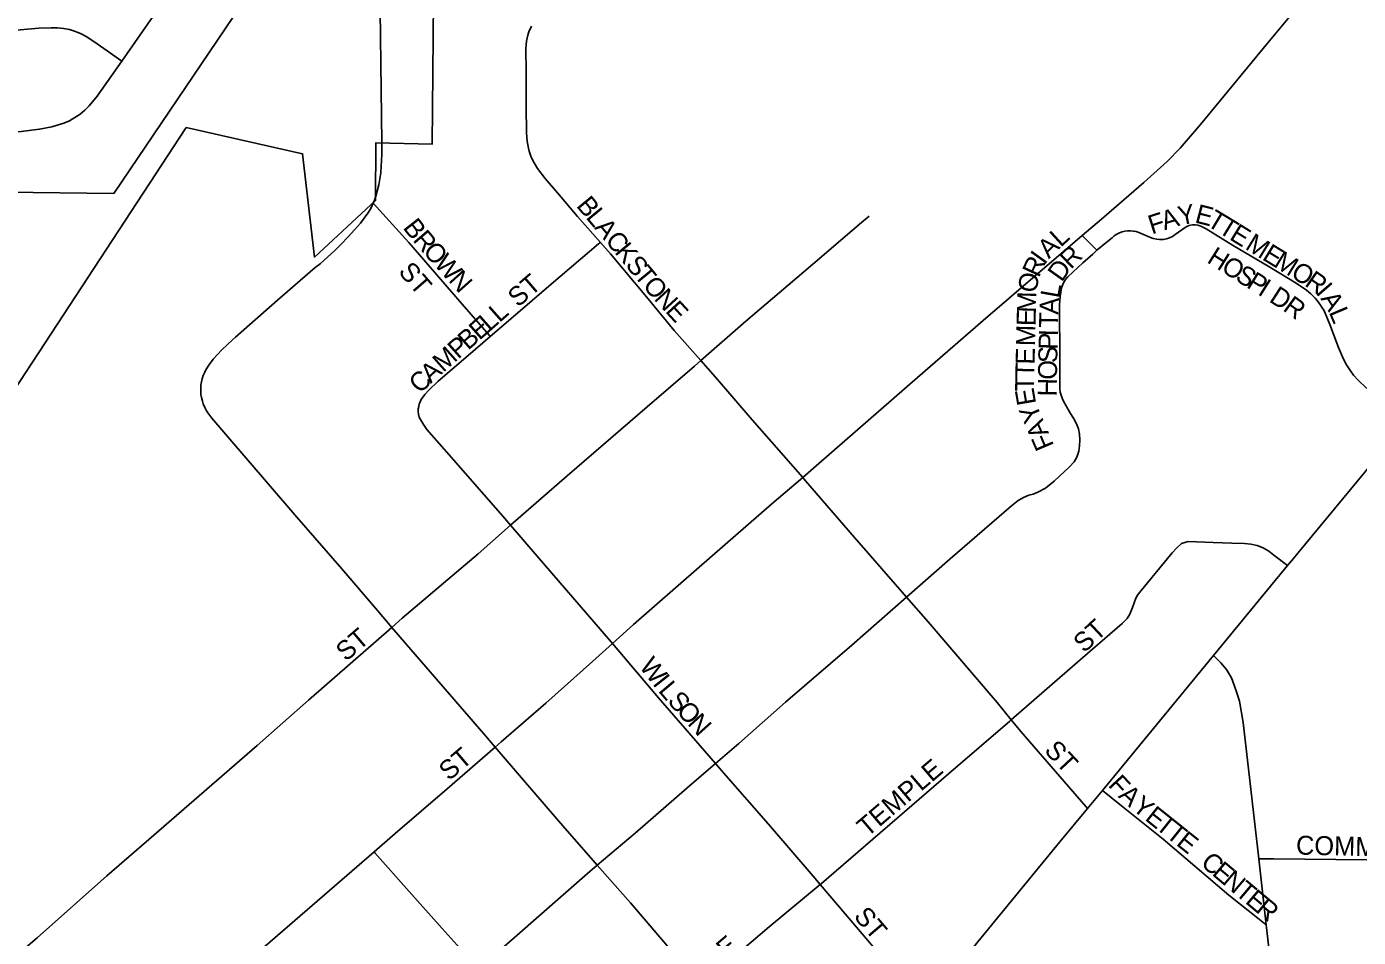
# Model space of a CAD drawing. Extents: x -51392 to 1635000, y 156707 to 696232.
# Drawn here: x 139153 to 142661, y 489774 to 492173 of the extents above; entities that cross this region are included whole.
import ezdxf

# ---------------------------------------------------------------- set-up
doc = ezdxf.new("R2010")
doc.units = 0
for name, color, linetype in [('GM_X_City_Street', 7, 'Continuous'), ('GM_X_City_Street_Text', 7, 'Continuous'), ('GM_X_Corporation', 7, 'Continuous'), ('GM_X_State_Route', 7, 'Continuous'), ('GM_X_US_Route', 7, 'Continuous')]:
    doc.layers.add(name, color=color, linetype=linetype)

msp = doc.modelspace()

# ---------------------------------------------------------------- linework, layer by layer
at = {"layer": 'GM_X_City_Street'}
for points in [[(141933.2, 491622.4), (141984, 491665.8), (142095.8, 491762.2), (142156.8, 491817.3), (142191.3, 491852.7), (142245.3, 491914.6), (142422.5, 492129.9), (142610.7, 492357.2), (142821, 492608.8), (142845.6, 492634.5)], [(139403.9, 492081.4), (139452.7, 492150.8), (139527, 492259.2), (139562.4, 492314.4), (139577.6, 492343.6), (139590.4, 492373.8), (139601, 492404.9), (139609.4, 492436.6), (139615.5, 492468.9), (139618.9, 492501.5), (139621.8, 492600), (139621.8, 492601.7)], [(138389, 492100.2), (138467.7, 492106.2), (138696, 492125.6), (138859.1, 492139.3), (139185.2, 492168.5), (139217.9, 492169.8), (139234.3, 492169.4), (139250.6, 492167.7), (139266.6, 492164.7), (139282.3, 492160), (139297.3, 492153.7), (139311.8, 492146), (139338.8, 492127.6), (139365.5, 492108.6), (139403.9, 492081.4)], [(140664.3, 491604.2), (140603.9, 491672.4), (140551.1, 491735.2), (140518.7, 491772.5), (140498.5, 491799.1), (140489.7, 491813.5), (140482.5, 491828.8), (140479.2, 491837.1), (140476.7, 491845), (140475.2, 491852.3), (140473.3, 491861.4), (140471.8, 491871), (140470.7, 491880.6), (140470, 491894.6), (140469.1, 491960.6), (140469.1, 492075.4), (140468.4, 492091.3), (140468.3, 492104.1), (140468.2, 492114.4), (140468.9, 492125.1), (140469.8, 492133.9), (140471.3, 492142), (140473.3, 492150.4), (140476.2, 492158.5), (140483, 492174)], [(138411.3, 491804.6), (138518.5, 491829.1), (138583.2, 491840.3), (138632, 491846.8), (138779.1, 491861.4), (138975.1, 491880.8), (139138.6, 491896.4), (139187.5, 491902.4), (139219.7, 491908.9), (139251.1, 491918.4), (139266.2, 491924.9), (139280.5, 491932.9), (139294, 491942.2), (139306.6, 491952.8), (139318.2, 491964.4), (139339.1, 491989.7), (139403.9, 492081.4)], [(140374.2, 491356.9), (140371.2, 491360.3), (140300, 491441.6), (140160.3, 491604.4), (140066.2, 491707.7)], [(140928.8, 491293), (141047.8, 491397.2), (141135.2, 491471.6), (141247.6, 491567.1), (141347.1, 491652.4), (141372.2, 491673.4)], [(141972.1, 491584), (141999.7, 491606.7), (142011.9, 491616.7), (142017.7, 491621.3), (142024.7, 491625.8), (142031.6, 491629.3), (142038.4, 491631.9), (142045.6, 491633.8), (142053, 491634.7), (142060.5, 491634.9), (142067.8, 491634.1), (142075, 491632.9), (142082.7, 491630.4), (142113.1, 491617.5), (142119.9, 491615.1), (142129.5, 491612.5), (142137, 491611.6), (142146.6, 491611.8), (142155.4, 491613.5), (142163.3, 491616.3), (142171.3, 491620.3), (142178.3, 491624.8), (142204.2, 491643.7), (142210.6, 491647.3), (142215.2, 491648.9), (142218.6, 491649.8), (142223.9, 491650.3), (142231.4, 491650.5), (142237.8, 491649.5), (142245.9, 491646.9), (142252.9, 491643.9), (142260.2, 491639.8), (142329.1, 491596.7), (142427.7, 491539), (142497.2, 491497.1), (142523.7, 491478.9), (142535.8, 491468.7), (142541.8, 491463), (142546.9, 491457.4), (142552.1, 491451.5), (142556.9, 491445.2), (142561.2, 491439.2), (142565.7, 491432.1), (142569.5, 491425.8), (142573.4, 491418.2), (142585.7, 491388.6), (142608.5, 491327.6), (142621.4, 491297.1), (142629.1, 491282.4), (142638.1, 491268.4), (142648.2, 491255.1), (142659.2, 491242.7), (142682.9, 491219.7)], [(141197.2, 490985.6), (141240, 491022.2), (141499.8, 491248.2), (141672.9, 491398.9), (141809.4, 491516.7), (141933.2, 491622.4)], [(141933.2, 491622.4), (141945.2, 491610.7), (141962.2, 491593.8), (141972.1, 491584)], [(140374.2, 491356.9), (140434.3, 491408.6), (140535, 491494.3), (140659.8, 491600.4), (140664.3, 491604.2)], [(140928.8, 491293), (140858.9, 491372.2), (140785.5, 491460.8), (140690.9, 491574.1), (140664.3, 491604.2)], [(141746.7, 490910.8), (141765.1, 490925.1), (141778.4, 490932.4), (141792.6, 490938.4), (141804, 490941.7), (141816.8, 490946.7), (141836.6, 490957.6), (141859.6, 490975.9), (141900.3, 491013.2), (141912, 491026.9), (141919.6, 491039.1), (141924.1, 491054.9), (141926.5, 491068.9), (141927.4, 491084.9), (141926.2, 491099.7), (141923.5, 491113.1), (141918.5, 491126.4), (141911.3, 491140), (141900, 491158), (141883.9, 491186.2), (141880.4, 491194), (141877.5, 491201.7), (141875.7, 491209.8), (141874.5, 491218.5), (141874.1, 491293.3), (141873.8, 491440.1), (141875, 491462.3), (141876.9, 491473), (141879.2, 491484.5), (141883.7, 491497.9), (141889, 491507), (141895.5, 491514.1), (141934.6, 491550.3), (141960.9, 491573.6), (141972.1, 491584)], [(140192.2, 491191.1), (140202.1, 491203.5), (140213, 491215.4), (140236.3, 491237.9), (140335.1, 491323.3), (140374.2, 491356.9)], [(140427.9, 490859.6), (140576.7, 490989.8), (140787.8, 491171.7), (140912.2, 491278.4), (140928.8, 491293)], [(141197.2, 490985.6), (141064, 491137.2), (140967.7, 491249.1), (140928.8, 491293)], [(140427.9, 490859.6), (140412.6, 490877.5), (140271.9, 491037.8), (140207.7, 491111.9), (140198.4, 491124.8), (140190.4, 491138), (140187.6, 491144.4), (140185.4, 491151.8), (140184.4, 491159.4), (140184.9, 491166.5), (140186.1, 491172.5), (140187.5, 491178.3), (140192.2, 491191.1)], [(140696.1, 490547.8), (140751.5, 490597.9), (140924.6, 490749), (141115.5, 490915.6), (141197.2, 490985.6)], [(141470.8, 490670.3), (141441.6, 490703.9), (141333.4, 490827.5), (141205, 490976.7), (141197.2, 490985.6)], [(141470.8, 490670.3), (141585.8, 490770.8), (141695.1, 490865.9), (141746.7, 490910.8)], [(140115.2, 490590.7), (140142.7, 490614.7), (140342.4, 490784.6), (140427.9, 490859.6)], [(140696.1, 490547.8), (140668.8, 490579.9), (140497.7, 490778.2), (140427.9, 490859.6)], [(142058.7, 490625.1), (142065.9, 490642.7), (142070.3, 490655.1), (142074.8, 490667.9), (142079, 490675.6), (142084.7, 490683.6), (142170.6, 490787), (142181.5, 490799.5), (142194.8, 490811.2), (142212.3, 490816.6), (142278.6, 490814.3), (142327.6, 490812.5), (142360.7, 490811.1), (142377.4, 490809.6), (142394.1, 490806.3), (142410.2, 490800.1), (142424.7, 490791.1), (142437.7, 490781.1), (142474, 490753.2)], [(140967.2, 490232.3), (141028.8, 490285.2), (141152.1, 490393.7), (141326.2, 490543.7), (141470.8, 490670.3)], [(141746.6, 490347), (141709, 490392.6), (141527.7, 490604.8), (141470.8, 490670.3)], [(141746.6, 490347), (141915, 490494.1), (142038.9, 490600.7), (142051.4, 490614.4), (142058.7, 490625.1)], [(139121.4, 489722.3), (139180.9, 489772.6), (139364.6, 489936), (139488.8, 490043), (139760.9, 490279.3), (139896.1, 490398.7), (140115.2, 490590.7)], [(140387, 490275.1), (140403.2, 490289.1), (140520.6, 490391.2), (140643.8, 490500.4), (140696.1, 490547.8)], [(140967.2, 490232.3), (140817.1, 490405.4), (140696.1, 490547.8)], [(142398.3, 489981.2), (142357.3, 490340), (142347.4, 490396.2), (142341.2, 490415.7), (142333.8, 490438.8), (142326.1, 490457.6), (142313.3, 490480), (142298.1, 490496.8), (142279.1, 490516.1)], [(141243.6, 489913.5), (141247.1, 489916.4), (141581.5, 490204.8), (141742.6, 490343.5), (141746.6, 490347)], [(141947.5, 490113.6), (141942.7, 490119.2), (141874.5, 490197.9), (141771.6, 490316.7), (141746.6, 490347)], [(140068.3, 489999.1), (140124.2, 490047.5), (140260.7, 490165.3), (140387, 490275.1)], [(140656.2, 489964.8), (140755.7, 490048.7), (140891.9, 490167.5), (140967.2, 490232.3)], [(141243.6, 489913.5), (141224.7, 489935.8), (141107.1, 490072.2), (140988.6, 490207.7), (140967.2, 490232.3)], [(141986.5, 490160.8), (142032.4, 490124.1), (142146.5, 490032.9), (142319.1, 489885.1), (142396.2, 489824.9), (142418.2, 489807.7)], [(139390.1, 489412.2), (139467.5, 489478.6), (139690.2, 489672.2), (139950.7, 489897.3), (140068.3, 489999.1)], [(140343.2, 489691.3), (140334.8, 489700.7), (140247.5, 489797.5), (140160.8, 489894.7), (140070.5, 489996.6), (140068.3, 489999.1)], [(140343.2, 489691.3), (140445.4, 489780), (140630.3, 489942.8), (140656.2, 489964.8)], [(142398.3, 489981.2), (142437.9, 489980.9), (142519.6, 489980.1), (142764.5, 489977.3), (142911.3, 489974.7), (143172.6, 489970.8), (143239.2, 489970.4)], [(142418.2, 489807.7), (142398.3, 489981.2)], [(140931, 489647), (140996.8, 489706), (141108.8, 489801.6), (141243.6, 489913.5)], [(141504.5, 489574.2), (141492.9, 489600.8), (141485.3, 489615), (141477.2, 489627.4), (141462.6, 489646.7), (141424.3, 489697.2), (141383.7, 489748.8), (141309.2, 489835.9), (141243.6, 489913.5)], [(142430.4, 489701), (142418.2, 489807.7)]]:
    msp.add_lwpolyline(points, dxfattribs=at)
at = {"layer": 'GM_X_Corporation'}
msp.add_lwpolyline([(139780.3, 492322.4), (139382.9, 491732.9), (138531.2, 491743.3), (138447.1, 490541.3), (138625.9, 490463), (138741, 490547.5), (138698.5, 490572.2), (139573.9, 491906.7), (139880, 491837.7), (139911.2, 491565.8), (140072.1, 491715), (140073.3, 491866.9), (140221.8, 491863.1), (140226.3, 492428.6)], dxfattribs=at)
at = {"layer": 'GM_X_State_Route'}
for points in [[(140089.1, 491867.4), (140082.4, 492354.8), (140081.9, 492392.3), (140081.3, 492432.4), (140081, 492479), (140080.7, 492519.1), (140080.4, 492561.8), (140078.9, 492611.9), (140078.3, 492632.8), (140078, 492662.4), (140076.6, 492797.1), (140073.8, 493049.2)], [(140085.9, 491788.9), (140088.7, 491836.3), (140089.1, 491867.4)], [(139926.3, 491548.3), (139965.6, 491583.8), (139981.8, 491600), (140000, 491618.7), (140016.6, 491637.3), (140032.4, 491655.4), (140051.7, 491681.3), (140059.7, 491693.5), (140063.5, 491701.8), (140066.2, 491707.7), (140069.2, 491715.8), (140073, 491726.4), (140080.6, 491755.7), (140085.8, 491787.6), (140085.9, 491788.9)], [(139695.6, 491347.9), (139703.4, 491355.2), (139814, 491452.7), (139913.7, 491537.9), (139926.3, 491548.3)], [(140077.6, 490634.8), (139983.6, 490744.8), (139865.4, 490880.9), (139790.4, 490967.5), (139683.1, 491092.7), (139640.8, 491141.8), (139631, 491155.4), (139626.2, 491162.9), (139622.4, 491170), (139618.6, 491179.4), (139616.4, 491186.3), (139613.8, 491195.8), (139612.4, 491203.6), (139611.9, 491210.5), (139611.9, 491220), (139612.4, 491228.2), (139613.8, 491237.2), (139615.8, 491245.2), (139618.6, 491253.7), (139621.7, 491261.1), (139625.4, 491268.9), (139633.1, 491281), (139644.6, 491296.8), (139667.3, 491321.3), (139695.6, 491347.9)], [(140645.8, 489976.6), (140571, 490061.8), (140462.2, 490188), (140387, 490275.1), (140357.1, 490309.9), (140153.8, 490545.6), (140115.2, 490590.7), (140077.6, 490634.8)], [(141213.4, 489321.8), (141043.4, 489517.4), (140931, 489647), (140893.1, 489690.7), (140744, 489864.8), (140656.2, 489964.8), (140645.8, 489976.6)]]:
    msp.add_lwpolyline(points, dxfattribs=at)
at = {"layer": 'GM_X_US_Route'}
for points in [[(142501, 490785.9), (142678, 490999.1), (142788.1, 491132.6), (142844.9, 491201.6), (143120.3, 491536.9)], [(141504.5, 489574.2), (141542.7, 489620.1), (141570.2, 489653.8), (141603.4, 489694.6), (141627.8, 489724.5), (141666.6, 489772), (141874.7, 490025.5), (141947.5, 490113.6), (141986.5, 490160.8), (142279.1, 490516.1), (142474, 490753.2), (142489.5, 490772.1), (142501, 490785.9)]]:
    msp.add_lwpolyline(points, dxfattribs=at)

# ---------------------------------------------------------------- texts
at = {"layer": 'GM_X_City_Street_Text'}
for s, rotation, p in [('B', 309.6041, (140599.2, 491700.3)), ('L', 309.6009, (140624.5, 491669.8)), ('F', 17.7638, (142116.5, 491625.2)), ('A', 17.757, (142150.1, 491635.9)), ('Y', 10.8238, (142190.4, 491648.9)), ('E', 345.535, (142227.8, 491657.4)), ('T', 329.153, (142258.5, 491650)), ('B', 308.1516, (140142.5, 491642.8)), ('A', 309.608, (140646.9, 491642.7)), ('T', 328.5158, (142288.5, 491632.1)), ('E', 328.4173, (142318.5, 491613.7)), ('R', 310.7131, (140168.5, 491609.8)), ('C', 309.6041, (140675, 491608.8)), ('K', 309.595, (140700.2, 491578.3)), ('A', 44.3637, (141845.5, 491559.5)), ('L', 42.4648, (141876.6, 491590)), ('M', 328.425, (142359.8, 491588.3)), ('O', 311.6839, (140194.9, 491579.1)), ('W', 311.7332, (140224.2, 491546.2)), ('I', 54.1672, (141834.1, 491543.4)), ('R', 44.3876, (141903.3, 491532)), ('H', 327.8427, (142259.2, 491553.1)), ('E', 328.4173, (142404.8, 491560.7)), ('M', 328.4293, (142434.8, 491542.3)), ('ST', 310.7862, (140130.3, 491526.1)), ('S', 309.5953, (140728.3, 491544.4)), ('T', 309.6009, (140750.7, 491517.3)), ('R', 65.1901, (141818.8, 491509.7)), ('D', 54.7265, (141879.4, 491497.9)), ('O', 327.8726, (142296.5, 491529.7)), ('S', 327.8641, (142333.7, 491506.3)), ('O', 328.4312, (142479.8, 491514.6)), ('N', 311.7322, (140262.3, 491503.5)), ('ST', 40.7779, (140447.6, 491431.7)), ('O', 310.76, (140773.9, 491489.3)), ('O', 80.2102, (141812.3, 491469.6)), ('P', 327.8411, (142363.5, 491487.5)), ('I', 327.8427, (142393.3, 491468.8)), ('R', 325.1307, (142516.6, 491492)), ('N', 312.4806, (140803.7, 491454.7)), ('M', 88.5711, (141811.2, 491418.7)), ('L', 79.9306, (141872, 491455.8)), ('D', 327.194, (142423, 491450.1)), ('I', 310.9597, (142546.7, 491471.5)), ('A', 301.8697, (142559.9, 491456.6)), ('L', 41.4867, (140398.5, 491391.6)), ('E', 312.5231, (140833.4, 491422.3)), ('A', 87.4775, (141870.2, 491413.6)), ('R', 323.7415, (142459.3, 491426.8)), ('L', 292.9083, (142582.1, 491421.1)), ('E', 41.5042, (140345.8, 491345)), ('L', 41.4777, (140372.2, 491368.3)), ('E', 88.5711, (141810.3, 491383.5)), ('T', 88.7896, (141869.5, 491378.7)), ('B', 41.49, (140316.1, 491318.8)), ('M', 88.593, (141809, 491330.8)), ('P', 88.7869, (141868.3, 491321.5)), ('I', 88.7982, (141869, 491356.7)), ('M', 41.5034, (140250.2, 491260.4)), ('P', 41.4777, (140289.8, 491295.4)), ('S', 88.7869, (141867.5, 491286.3)), ('E', 88.5711, (141807.8, 491282.3)), ('O', 88.7861, (141866.6, 491242.3)), ('C', 43.8039, (140189.2, 491204.1)), ('A', 41.78, (140217.5, 491231.2)), ('T', 88.5711, (141806.9, 491247.2)), ('E', 99.6461, (141812.3, 491179.8)), ('T', 89.4731, (141806.6, 491212.2)), ('H', 88.7896, (141865.7, 491198.3)), ('Y', 113.1517, (141828.7, 491142.3)), ('A', 113.1705, (141846.1, 491101.9)), ('F', 113.1416, (141859.9, 491069.5)), ('ST', 40.3567, (139994.4, 490499.1)), ('ST', 43.0506, (141938.7, 490521.5)), ('W', 308.0272, (140764.8, 490487.2)), ('I', 308.2015, (140800.2, 490442)), ('L', 310.3402, (140815.1, 490423.2)), ('S', 311.9698, (140838.9, 490395.1)), ('O', 312.0186, (140862.4, 490368.9)), ('N', 312.0504, (140891.9, 490336.2)), ('ST', 40.3369, (140265.7, 490184.8)), ('ST', 313.0506, (141831.2, 490264.7)), ('TEMPLE', 40.4545, (141367.2, 490036.7)), ('F', 312.7755, (141999.4, 490173.7)), ('A', 317.3069, (142026.3, 490144.8)), ('Y', 321.2903, (142061.6, 490112.5)), ('E', 321.3259, (142095.9, 490085)), ('T', 321.3241, (142123.4, 490063)), ('T', 321.3241, (142150.9, 490041)), ('E', 321.3613, (142178.4, 490019)), ('COMMERCIAL', 358.7651, (142496, 489992.3)), ('C', 319.853, (142242.5, 489965.7)), ('E', 319.8513, (142272.7, 489940.1)), ('N', 319.8468, (142299.6, 489917.4)), ('T', 319.8513, (142333.3, 489889.1)), ('E', 319.8513, (142360.2, 489866.4)), ('ST', 310.337, (141329.6, 489828.4)), ('R', 320.7511, (142387.7, 489843.1)), ('E', 40.3477, (140996.2, 489716.4))]:
    msp.add_text(s, height=50, rotation=rotation, dxfattribs=at).set_placement(p)

doc.saveas('drawing.dxf')
